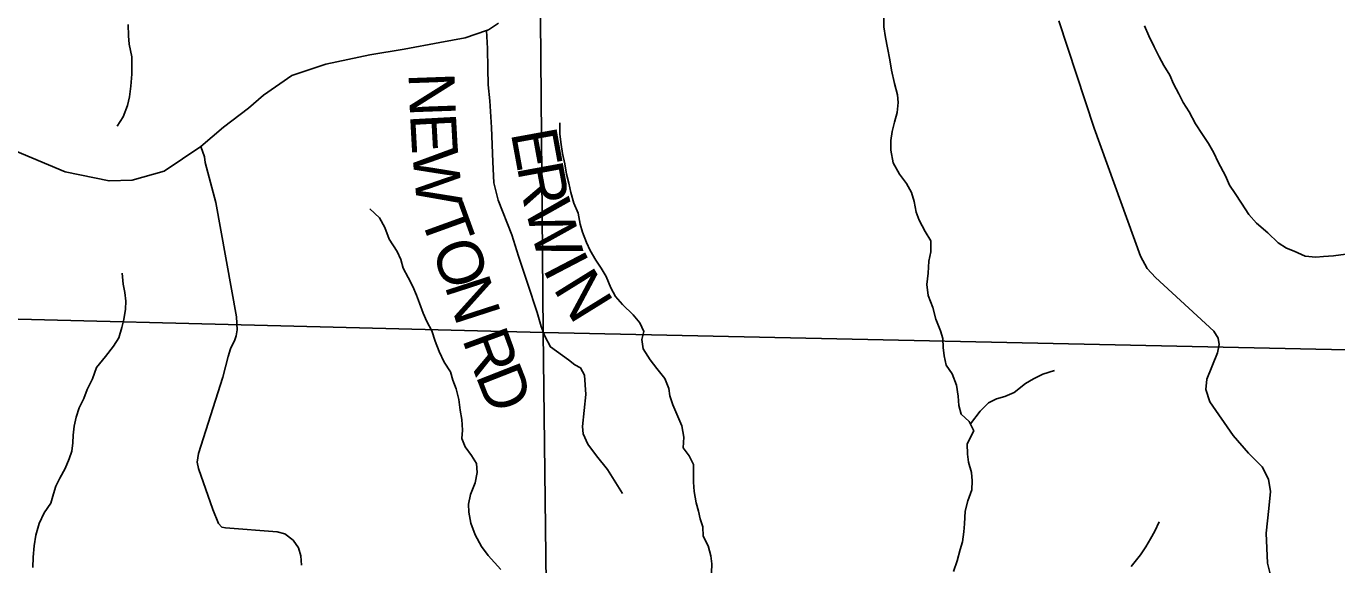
# Model space of a CAD drawing. Extents: x 2043100 to 2470832, y 443715 to 810583.
# Drawn here: x 2233197 to 2241776, y 587900 to 591429 of the extents above; entities that cross this region are included whole.
import ezdxf

# ---------------------------------------------------------------- set-up
doc = ezdxf.new("R2010")
doc.units = 0
for name, color, linetype in [('GM_X_County_Road', 7, 'Continuous'), ('GM_X_Minor_River', 7, 'Continuous'), ('GM_X_Section', 7, 'Continuous'), ('GM_X_State_Route', 7, 'Continuous'), ('GM_X_Township_Road', 7, 'Continuous'), ('GM_X_Township_Road_Text', 7, 'Continuous')]:
    doc.layers.add(name, color=color, linetype=linetype)

msp = doc.modelspace()

# ---------------------------------------------------------------- linework, layer by layer
at = {"layer": 'GM_X_County_Road'}
msp.add_lwpolyline([(2239956.3, 591463.1), (2240187.6, 590760.1), (2240490.7, 589921), (2240534.6, 589840.8), (2240588.5, 589782.7), (2240970.2, 589430), (2241000.1, 589383.9), (2241006.1, 589343.8), (2240996, 589287.8), (2240925.8, 589115.7), (2240919.8, 589047.6), (2240945.7, 588967.5), (2241097.5, 588747.1), (2241197.3, 588630.9), (2241287.3, 588540.7), (2241329.2, 588460.6), (2241343.1, 588380.5), (2241331, 588268.4), (2241312.8, 588106.3), (2241322.6, 587910), (2241348.5, 587805.9)], dxfattribs=at)
at = {"layer": 'GM_X_Minor_River'}
for points in [[(2239268, 587855), (2239291.8, 587925.1), (2239311.6, 587999.2), (2239325.5, 588051.2), (2239335.3, 588115.3), (2239339.1, 588167.3), (2239342.9, 588251.4), (2239360.7, 588319.4), (2239386.5, 588391.6), (2239390.3, 588449.6), (2239384.2, 588503.6), (2239366, 588571.6), (2239357.8, 588623.6), (2239357.6, 588691.6), (2239399.4, 588777.8), (2239369.2, 588839.7), (2239317.1, 588887.6), (2239300.9, 588943.6), (2239298.7, 589005.6), (2239286.5, 589077.6), (2239258.3, 589151.5), (2239220.1, 589207.4), (2239206, 589269.4), (2239199.8, 589323.4), (2239197.6, 589381.5), (2239181.5, 589433.4), (2239151.3, 589509.4), (2239131, 589585.3), (2239100.8, 589665.3), (2239092.6, 589737.3), (2239100.4, 589811.4), (2239106.2, 589889.4), (2239118, 589949.5), (2239117.8, 590021.5), (2239081.6, 590083.4), (2239041.4, 590157.3), (2239023.2, 590211.3), (2239009, 590281.3), (2238992.8, 590339.3), (2238958.7, 590399.2), (2238912.5, 590459.1), (2238872.3, 590533), (2238856, 590617), (2238855.9, 590681), (2238865.7, 590739.1), (2238881.5, 590799.2), (2238897.3, 590863.2), (2238905.2, 590929.3), (2238901, 590979.3), (2238880.8, 591053.3), (2238860.5, 591141.2), (2238850.3, 591209.3), (2238834.1, 591287.2), (2238821.9, 591355.2), (2238811.7, 591425.2), (2238811.5, 591505.3)], [(2233865.2, 591440.5), (2233867.5, 591366.5), (2233871.6, 591310.5), (2233887.9, 591228.5), (2233888.2, 591114.4), (2233882.4, 591036.4), (2233872.6, 590966.3), (2233860.8, 590908.3), (2233831, 590834.2), (2233793.2, 590774)], [(2241834.5, 589935.2), (2241754.2, 589925.3), (2241690.2, 589919.1), (2241638.2, 589914.9), (2241570.2, 589922.8), (2241498.1, 589954.6), (2241448, 589974.4), (2241391.9, 590010.3), (2241323.7, 590074.1), (2241251.5, 590137.9), (2241201.4, 590195.8), (2241153.2, 590269.7), (2241111, 590333.6), (2241074.8, 590387.5), (2241046.6, 590447.4), (2241000.4, 590537.3), (2240972.2, 590599.3), (2240936, 590659.2), (2240897.8, 590719.1), (2240851.6, 590789), (2240809.4, 590866.9), (2240771.2, 590928.8), (2240743.1, 590984.8), (2240706.9, 591050.7), (2240682.7, 591108.7), (2240644.5, 591170.6), (2240612.4, 591228.5), (2240580.2, 591294.4), (2240546, 591366.4), (2240517.8, 591430.3)], [(2237682, 587848.2), (2237685.8, 587906.3), (2237677.6, 587958.3), (2237661.4, 588024.3), (2237629.3, 588088.2), (2237625.1, 588148.2), (2237608.9, 588200.2), (2237596.8, 588252.2), (2237582.6, 588306.2), (2237568.4, 588380.2), (2237564.2, 588440.2), (2237566.1, 588492.2), (2237565.9, 588556.2), (2237535.7, 588614.2), (2237497.6, 588666.1), (2237501.4, 588736.1), (2237489.2, 588810.1), (2237463, 588872), (2237428.8, 588948), (2237410.6, 589006), (2237402.5, 589056), (2237378.3, 589119.9), (2237324.1, 589185.8), (2237281.9, 589241.7), (2237235.7, 589315.6), (2237227.5, 589375.6), (2237239.4, 589427.7), (2237213.2, 589485.6), (2237171.1, 589537.5), (2237100.8, 589605.3), (2237054.7, 589657.2), (2237024.5, 589715.2), (2236992.3, 589789.1), (2236960.2, 589843), (2236926, 589894.9), (2236887.8, 589958.8), (2236863.7, 590010.8), (2236837.5, 590078.8), (2236823.3, 590130.7), (2236811.1, 590202.7), (2236780.9, 590268.7), (2236762.7, 590338.7), (2236748.5, 590400.6), (2236734.4, 590458.6), (2236722.2, 590526.6), (2236708, 590594.6), (2236699.8, 590654.6), (2236689.6, 590720.6), (2236689.4, 590796.7)], [(2236303.8, 587868.1), (2236221.5, 587959.9), (2236177.3, 588019.8), (2236135.1, 588095.8), (2236106.9, 588171.7), (2236094.7, 588243.7), (2236092.5, 588297.7), (2236104.4, 588359.8), (2236136.1, 588437.9), (2236149.9, 588504), (2236143.8, 588564), (2236111.6, 588615.9), (2236069.5, 588671.8), (2236049.3, 588727.8), (2236053.1, 588781.8), (2236048.9, 588851.8), (2236036.8, 588913.8), (2236028.5, 588983.8), (2236012.4, 589051.8), (2235990.2, 589109.8), (2235974, 589163.8), (2235933.8, 589227.7), (2235899.6, 589297.6), (2235873.4, 589365.6), (2235853.2, 589433.5), (2235819.1, 589493.4), (2235794.9, 589549.4), (2235770.7, 589613.4), (2235752.6, 589667.3), (2235728.4, 589723.3), (2235696.2, 589781.2), (2235664.1, 589843.2), (2235649.9, 589901.1), (2235625.7, 589953.1), (2235573.5, 590033), (2235545.3, 590110.9), (2235509.1, 590172.8), (2235446.9, 590232.7)], [(2233239.4, 587881), (2233243.2, 587949), (2233249, 588025.1), (2233258.8, 588093.2), (2233282.6, 588171.3), (2233314.4, 588239.4), (2233358.2, 588303.5), (2233376, 588365.6), (2233389.9, 588415.7), (2233417.7, 588467.8), (2233451.6, 588529.9), (2233477.4, 588594), (2233495.2, 588644.1), (2233501.1, 588698.2), (2233505, 588748.2), (2233510.8, 588808.2), (2233524.6, 588866.3), (2233544.4, 588928.4), (2233574.3, 588990.5), (2233596.1, 589048.6), (2233629.9, 589118.8), (2233657.7, 589192.9), (2233715.5, 589265.1), (2233769.3, 589331.3), (2233803.2, 589387.4), (2233823, 589455.5), (2233836.8, 589507.5), (2233846.6, 589575.6), (2233848.5, 589627.6), (2233842.3, 589683.7), (2233832.1, 589737.6), (2233823.9, 589809.7)], [(2239377.3, 588823.1), (2239441, 588906), (2239496.9, 588960.2), (2239548.8, 588986.3), (2239602.7, 589002.5), (2239664.7, 589028.7), (2239738.5, 589086.9), (2239790.4, 589119.1), (2239852.3, 589149.3), (2239928.3, 589173.5)], [(2240430, 587888.4), (2240491.8, 587964.7), (2240525.6, 588016.8), (2240557.5, 588070.9), (2240585.3, 588121), (2240613.2, 588181.1)]]:
    msp.add_lwpolyline(points, dxfattribs=at)
at = {"layer": 'GM_X_Section'}
for points in [[(2236536.1, 594818.9), (2236581.8, 589422.3), (2231252.3, 589556.9), (2231206.2, 594993.6)], [(2241842.1, 594627.9), (2241842.9, 589308.9), (2236581.8, 589422.3), (2236536.1, 594818.9)], [(2231252.3, 589556.9), (2236581.8, 589422.3), (2236644.8, 584122.9), (2231332.3, 584367.7)], [(2236581.8, 589422.3), (2241842.9, 589308.9), (2241878.2, 583993.2), (2236644.8, 584122.9)]]:
    msp.add_lwpolyline(points, close=True, dxfattribs=at)
at = {"layer": 'GM_X_State_Route'}
msp.add_lwpolyline([(2233125.1, 590611.9), (2233451.4, 590475.5), (2233738.8, 590414.7), (2233891.1, 590420.5), (2234098.9, 590479), (2234340.9, 590639.8), (2234488.5, 590768.2), (2234651.4, 590892.3), (2234750.7, 590977.7), (2234935.6, 591106.1), (2235159.3, 591180.9), (2235445.3, 591240.3), (2235671.4, 591279), (2235905.4, 591321.9), (2236069.4, 591351.8), (2236210.9, 591401.4), (2236223.2, 591405.7), (2236288.8, 591448.6)], dxfattribs=at)
at = {"layer": 'GM_X_Township_Road'}
for points in [[(2236210.9, 591401.4), (2236216.5, 591283.1), (2236219.2, 591151), (2236221.7, 591044.9), (2236232.3, 590938.9), (2236243.2, 590764.8), (2236252.4, 590540.6), (2236257.1, 590402.5), (2236285.7, 590288.6), (2236374.8, 590060.9), (2236419.6, 589921), (2236478.5, 589745.2), (2236541.5, 589553.3), (2236567.9, 589461.4), (2236592.3, 589397.5), (2236628.6, 589327.6), (2236747.1, 589242.2), (2236789.2, 589210.4), (2236825.3, 589190.6), (2236851.6, 589142.7), (2236860.3, 589014.6), (2236837.4, 588806.3), (2236843.6, 588758.3), (2236874, 588690.4), (2236930.4, 588612.7), (2237002.8, 588525), (2237099.6, 588367.4)], [(2234998, 587896.4), (2234994.1, 587958.4), (2234980.2, 588010.5), (2234944.2, 588060.6), (2234890.3, 588102.7), (2234840.3, 588116.7), (2234502.3, 588141.1), (2234478.3, 588147.1), (2234456.3, 588171.2), (2234418.4, 588261.3), (2234324.7, 588531.7), (2234316.7, 588571.7), (2234324.8, 588629.8), (2234483.3, 589130.2), (2234519.5, 589264.3), (2234533.5, 589314.3), (2234563.6, 589374.3), (2234571.6, 589400.4), (2234577.7, 589438.4), (2234573.8, 589524.5), (2234438.5, 590273.4), (2234368.8, 590535.7), (2234362.9, 590573.8), (2234340.9, 590639.8)]]:
    msp.add_lwpolyline(points, dxfattribs=at)

# ---------------------------------------------------------------- texts
at = {"layer": 'GM_X_Township_Road_Text'}
for s, rotation, p in [('N', 272.06596, (2235699.4, 591121.4)), ('E', 273.12866, (2235709.2, 590851.5)), ('E', 280.33744, (2236368.2, 590731.2)), ('W', 275.12582, (2235722.3, 590616.1)), ('R', 280.4409, (2236408.6, 590509.9)), ('T', 289.91194, (2235771.6, 590187.5)), ('W', 284.72951, (2236458.5, 590244)), ('O', 289.08237, (2235847.7, 589977.6)), ('I', 297.57885, (2236572.9, 589840.6)), ('N', 301.80157, (2236641.7, 589710.8)), ('N', 287.94536, (2235933.5, 589729.6)), ('R', 290.18102, (2236048.4, 589378.8)), ('D', 291.46753, (2236136, 589140.7))]:
    msp.add_text(s, height=300, rotation=rotation, dxfattribs=at).set_placement(p)

doc.saveas('drawing.dxf')
